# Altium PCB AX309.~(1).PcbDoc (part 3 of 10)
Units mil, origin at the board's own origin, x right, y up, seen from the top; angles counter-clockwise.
Board outline 5185 x 3614 mil, 4 copper layers (Top Layer, GND, Mid-Layer 1, Bottom Layer); 191 components, 352 nets, 1106 pads, 425 vias.
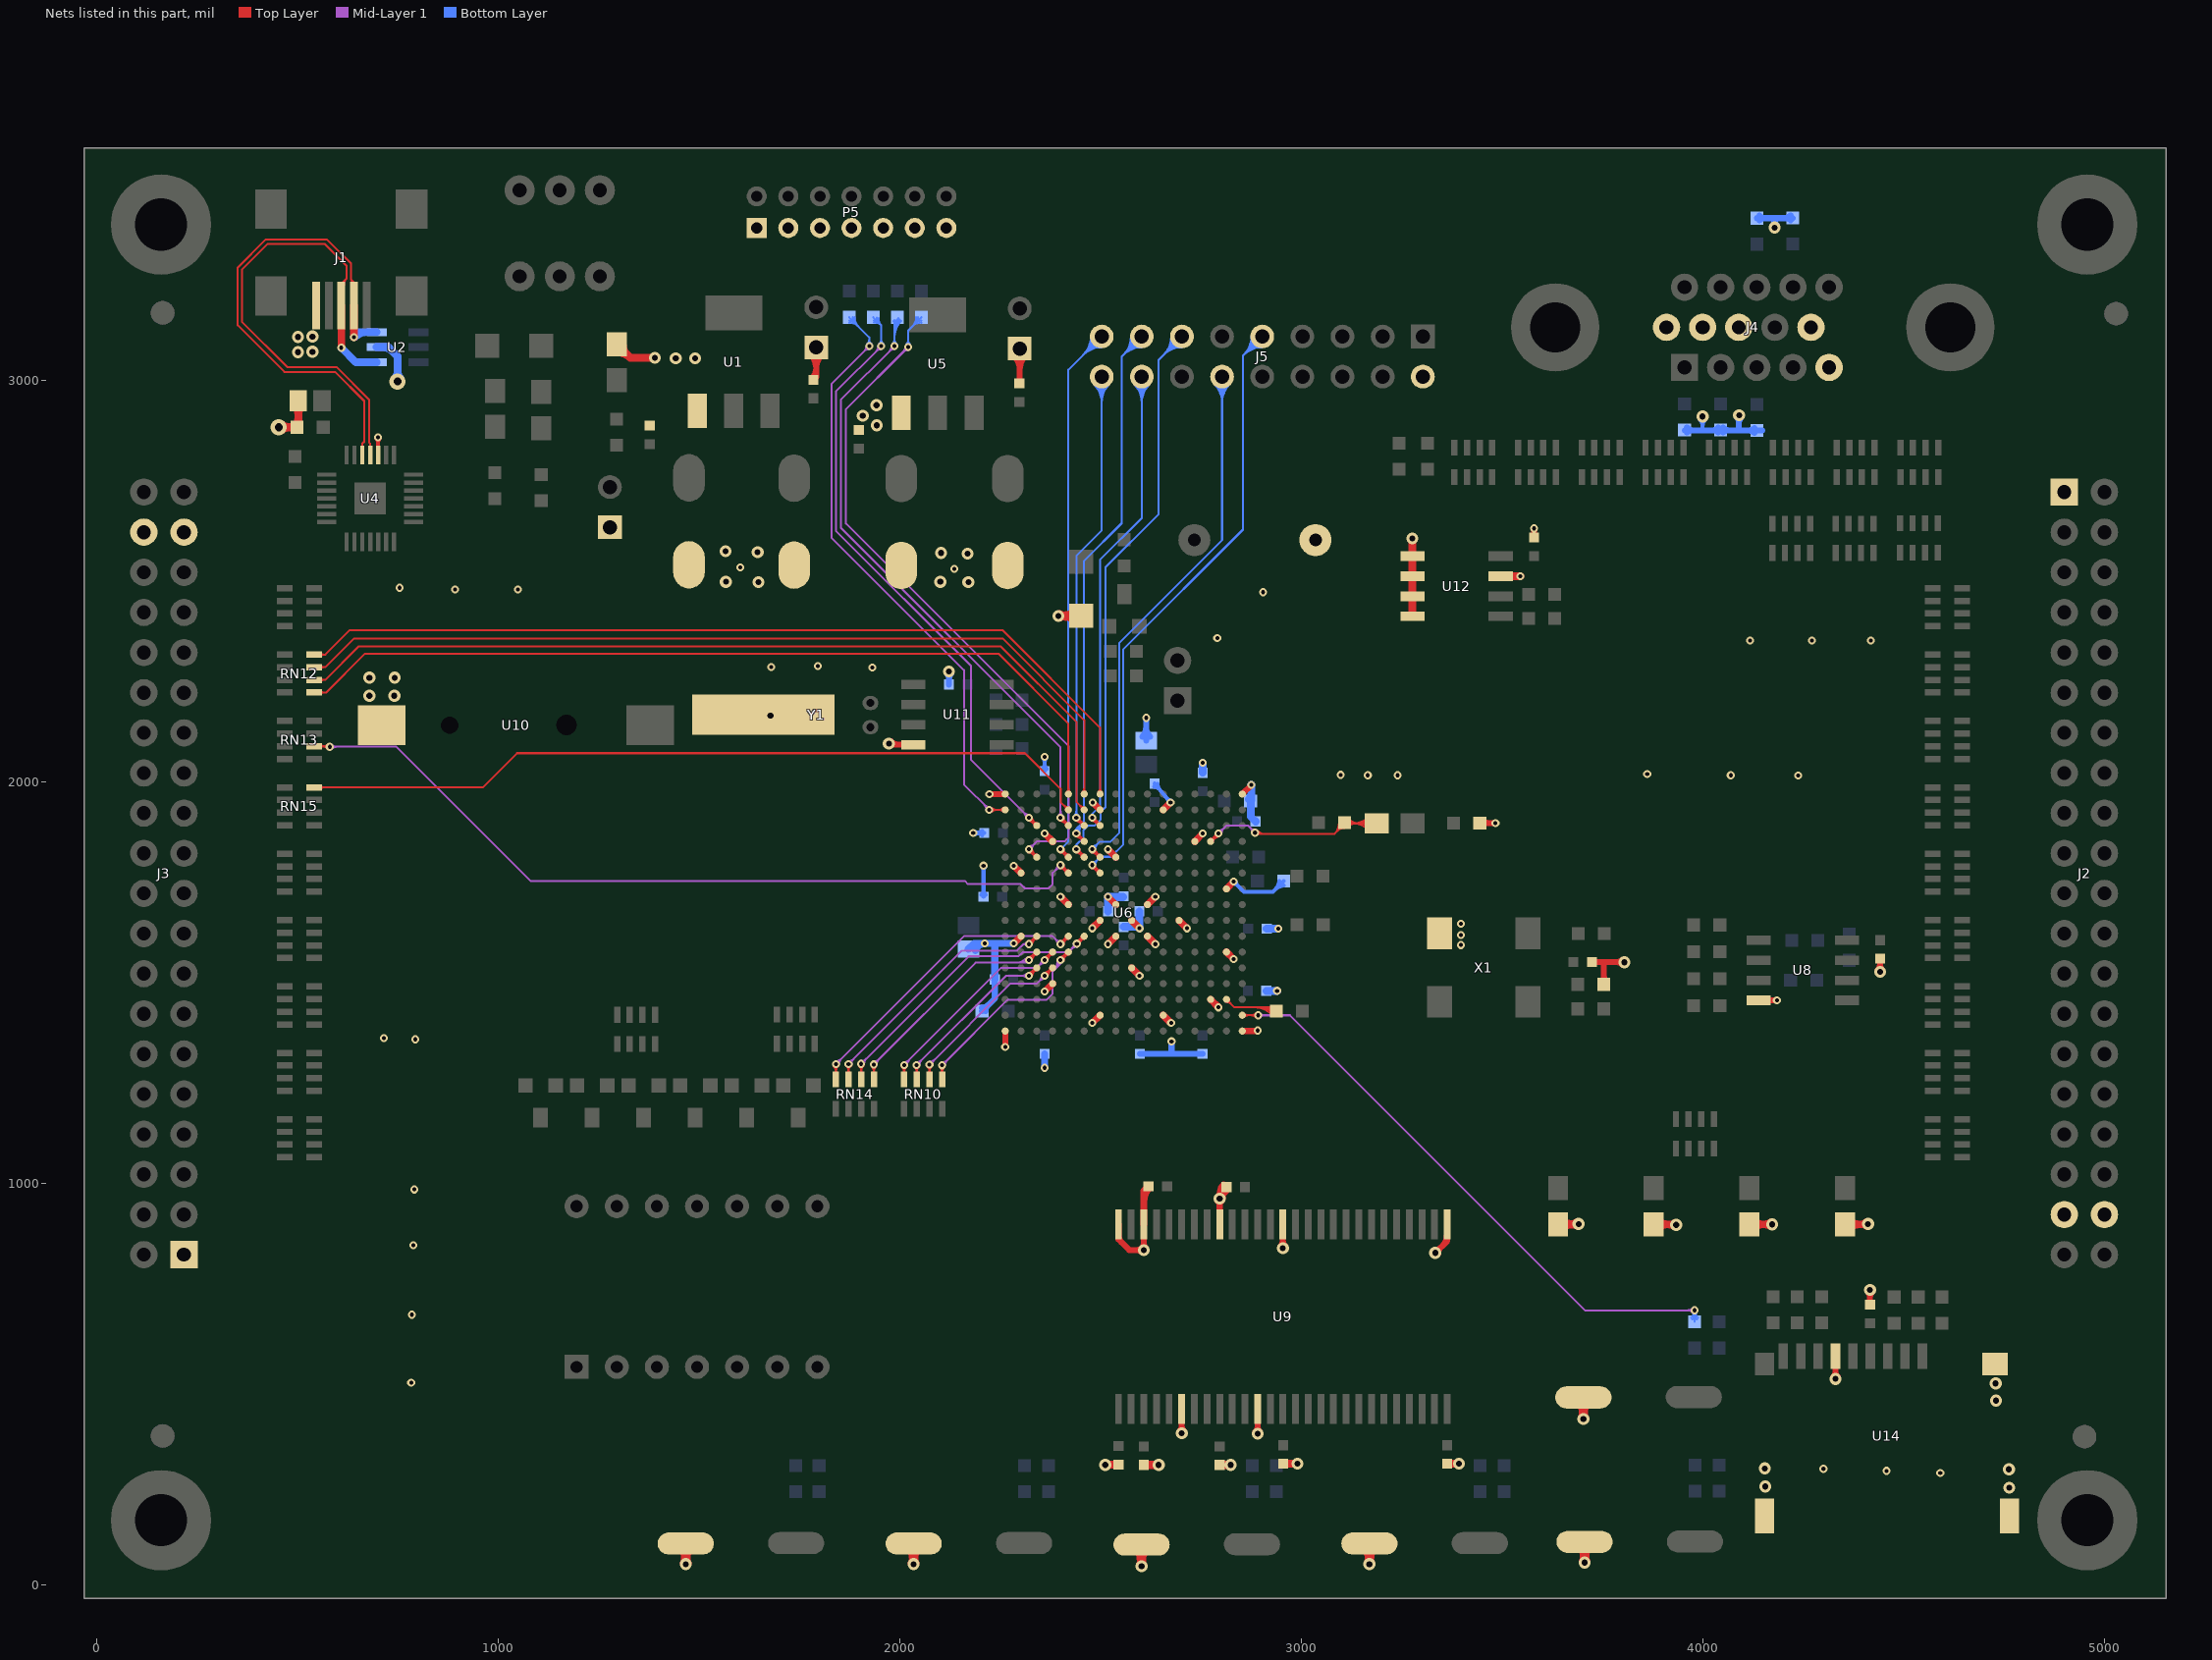
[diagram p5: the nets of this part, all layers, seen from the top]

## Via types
v1: diameter 20, hole 10, Top Layer to Bottom Layer, 328 vias
v2: diameter 30, hole 15, Top Layer to Bottom Layer, 95 vias
v3: diameter 40, hole 20, Top Layer to Bottom Layer, 2 vias

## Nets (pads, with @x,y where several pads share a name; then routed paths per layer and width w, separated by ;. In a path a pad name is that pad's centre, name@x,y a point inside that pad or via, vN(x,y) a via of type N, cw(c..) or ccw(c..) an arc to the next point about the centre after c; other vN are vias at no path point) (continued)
DIG0: RN14.7 U6.C7 | length 885.6
  Top Layer w5: v1@1867.19,1291.19 cw(c1854.39,1278.39) 1872.5,1278.39 cw(c1890.6,1278.39) v1@1877.8,1291.19 ; RN14.7@1868.7,1273.76 ccw(c1859.52,1282.93) 1872.5,1282.93 ccw(c1885.47,1282.93) RN14.7@1876.3,1273.76 ; RN14.7@1872.5,1258.15 v1(1872.5,1296.5) ; v1@2320.77,1602.69 ccw(c2318.06,1622.67) U6.C7@2335.52,1612.59 ; v1@2321.44,1597.74 ccw(c2319.79,1609.9) 2330.42,1603.76 ; v1(2321.78,1595.26) U6.C7@2341.46,1614.94 ; v1@2321.78,1602.76 ccw(c2321.78,1620.87) 2334.58,1608.06 ccw(c2347.39,1595.26) v1@2329.28,1595.26 ; v1@2323.75,1602.5 ccw(c2325.56,1609.16) 2331.54,1605.71 ; v1@2324.26,1594.92 cw(c2336.42,1593.27) 2330.28,1603.9 ; v1@2329.02,1597.23 cw(c2335.68,1599.04) 2332.23,1605.02 ; v1@2329.21,1594.25 cw(c2349.19,1591.54) U6.C7@2339.11,1609 ; U6.C7@2335.11,1614.94 cw(c2319.76,1614.94) 2330.61,1604.09 cw(c2341.46,1593.24) U6.C7@2341.46,1608.59 ; v1@2323.72,1602.5 ccw(c2325.55,1609.33) 2329.08,1603.21 cw(c2325.55,1609.33) v1@2323.72,1602.5 ; v1@2329.02,1597.2 cw(c2335.85,1599.03) 2329.73,1602.56 ccw(c2335.85,1599.03) v1@2329.02,1597.2
  Mid-Layer 1 w5: v1(1872.5,1296.5) 2155,1579 2292,1579 2308.26,1595.26 ; v1@1872.5,1304 ccw(c1872.5,1322.1) 1885.3,1309.3 ccw(c1898.1,1296.5) v1@1880,1296.5 ; v1@2315.42,1591.29 ccw(c2308.26,1586.82) 2308.26,1595.26 ; v1@2315.42,1599.23 cw(c2308.26,1603.69) 2308.26,1595.26 ; v1(2321.78,1595.26) 2308.26,1595.26
DIG1: RN10.5 U6.E6 | length 801.5
  Top Layer w5: v1@2100.18,1288.18 cw(c2087.38,1275.38) 2105.49,1275.38 cw(c2123.59,1275.38) v1@2110.79,1288.18 ; RN10.5@2101.69,1273.76 ccw(c2092.51,1282.93) 2105.49,1282.93 ccw(c2118.46,1282.93) RN10.5@2109.29,1273.76 ; RN10.5@2105.49,1258.15 v1(2105.49,1293.49) ; v1@2399.51,1563.32 ccw(c2396.8,1583.3) U6.E6@2414.26,1573.22 ; v1@2400.18,1558.37 ccw(c2398.53,1570.53) 2409.16,1564.39 ; v1(2400.52,1555.89) U6.E6@2420.2,1575.57 ; v1@2400.52,1563.39 ccw(c2400.52,1581.5) 2413.32,1568.69 ccw(c2426.13,1555.89) v1@2408.02,1555.89 ; v1@2402.49,1563.13 ccw(c2404.3,1569.79) 2410.28,1566.34 ; v1@2403,1555.55 cw(c2415.16,1553.9) 2409.02,1564.53 ; v1@2407.95,1554.88 cw(c2427.93,1552.17) U6.E6@2417.85,1569.63 ; 2410.97,1565.65 ccw(c2414.42,1559.67) v1@2407.76,1557.86 ; U6.E6@2413.85,1575.57 cw(c2398.5,1575.57) 2409.35,1564.72 cw(c2420.2,1553.87) U6.E6@2420.2,1569.22 ; v1@2407.76,1557.83 cw(c2414.59,1559.66) 2408.47,1563.19 ccw(c2414.59,1559.66) v1@2407.76,1557.83 ; v1@2402.46,1563.13 ccw(c2404.29,1569.96) 2407.82,1563.84 cw(c2404.29,1569.96) v1@2402.46,1563.13
  Mid-Layer 1 w5: v1(2105.49,1293.49) 2269,1457 2366,1457 2381,1472 2381,1527 2400.52,1546.52 v1(2400.52,1555.89) ; v1@2105.49,1300.99 ccw(c2105.49,1319.09) 2118.29,1306.29 ccw(c2131.09,1293.49) v1@2112.99,1293.49 ; 2381.09,1527.09 ccw(c2352.29,1555.89) v1@2393.02,1555.89 ; 2389.63,1535.63 ccw(c2369.36,1555.89) v1@2398.02,1555.89 ; 2398.16,1544.16 ccw(c2386.43,1555.89) v1@2403.02,1555.89
DIG2: RN10.7 U6.C5 | length 695.9
  Top Layer w5: v1@2036.7,1288.7 cw(c2022.7,1274.7) RN10.7@2042.5,1274.7 ; RN10.7@2038.7,1273.76 ccw(c2029.52,1282.93) 2042.5,1282.93 ccw(c2055.47,1282.93) RN10.7@2046.3,1273.76 ; RN10.7@2042.5,1258.15 v1@2042.5,1296.5 ; RN10.7@2042.5,1277.09 cw(c2058.91,1277.09) v1@2047.3,1288.7 ; v1@2320.77,1523.95 ccw(c2318.06,1543.93) U6.C5@2335.52,1533.85 ; v1@2321.44,1519 ccw(c2319.79,1531.16) 2330.42,1525.02 ; v1(2321.78,1516.52) U6.C5@2341.46,1536.2 ; v1@2321.78,1524.02 ccw(c2321.78,1542.13) 2334.58,1529.32 ccw(c2347.39,1516.52) v1@2329.28,1516.52 ; v1@2323.75,1523.76 ccw(c2325.56,1530.42) 2331.54,1526.97 ; v1@2324.26,1516.18 cw(c2336.42,1514.53) 2330.28,1525.16 ; v1@2329.02,1518.49 cw(c2335.68,1520.3) 2332.23,1526.28 ; v1@2329.21,1515.51 cw(c2349.19,1512.8) U6.C5@2339.11,1530.26 ; U6.C5@2335.11,1536.2 cw(c2319.76,1536.2) 2330.61,1525.35 cw(c2341.46,1514.5) U6.C5@2341.46,1529.85 ; v1@2323.72,1523.76 ccw(c2325.55,1530.59) 2329.08,1524.47 cw(c2325.55,1530.59) v1@2323.72,1523.76 ; v1@2329.02,1518.46 cw(c2335.85,1520.29) 2329.73,1523.82 ccw(c2335.85,1520.29) v1@2329.02,1518.46
  Mid-Layer 1 w5: v1(2042,1294) 2264.52,1516.52 v1(2321.78,1516.52) ; v1@2042,1301.5 ccw(c2042,1319.61) 2054.8,1306.8 ccw(c2067.61,1294) v1@2049.5,1294 ; v1@2316.48,1511.22 ccw(c2303.67,1498.41) 2303.67,1516.52 ccw(c2303.67,1534.63) v1@2316.48,1521.82
DIG3: RN14.6 U6.F7 | length 976.8
  Top Layer w5: v1@1898.69,1291.69 cw(c1885.89,1278.89) 1903.99,1278.89 cw(c1922.1,1278.89) v1@1909.3,1291.69 ; RN14.6@1900.19,1273.76 ccw(c1891.02,1282.93) 1903.99,1282.93 ccw(c1916.97,1282.93) RN14.6@1907.79,1273.76 ; RN14.6@1903.99,1258.15 v1(1903.99,1296.99) ; v1@2440.26,1603.83 ccw(c2438.55,1621.02) U6.F7@2453.51,1612.38 ; v1@2440.75,1598.86 ccw(c2439.74,1609.08) 2448.64,1603.95 ; v1(2441,1596.37) U6.F7@2459.57,1614.94 ; v1@2441,1603.87 ccw(c2441,1621.98) 2453.8,1609.17 ccw(c2466.61,1596.37) v1@2448.5,1596.37 ; v1@2443.49,1596.12 cw(c2453.71,1595.11) 2448.58,1604.01 ; v1@2443.64,1603.39 ccw(c2445.34,1607.93) 2449.54,1605.5 ; v1@2448.02,1599.01 cw(c2452.56,1600.71) 2450.13,1604.91 ; v1@2448.46,1595.63 cw(c2465.65,1593.92) U6.F7@2457.01,1608.88 ; U6.F7@2453.22,1614.94 cw(c2437.87,1614.94) 2448.72,1604.09 cw(c2459.57,1593.24) U6.F7@2459.57,1608.59 ; v1@2442.94,1603.61 ccw(c2445.13,1611.78) 2449.36,1604.46 cw(c2445.13,1611.78) v1@2442.94,1603.61 ; v1@2448.24,1598.31 cw(c2456.41,1600.5) 2449.09,1604.73 ccw(c2456.41,1600.5) v1@2448.24,1598.31
  Mid-Layer 1 w5: v1(1903.99,1296.99) 2172,1565 2296,1565 2306,1575 2419.63,1575 v1(2441,1596.37) ; v1@1903.99,1304.49 ccw(c1903.99,1322.6) 1916.8,1309.8 ccw(c1929.6,1296.99) v1@1911.49,1296.99 ; v1@2433.5,1596.37 cw(c2415.39,1596.37) 2428.2,1583.57 cw(c2441,1570.76) v1@2441,1588.87
DIG4: RN10.8 U6.D6 | length 780.1
  Top Layer w5: v1@2005.7,1288.7 cw(c1992.89,1275.89) 2011,1275.89 cw(c2029.11,1275.89) v1@2016.3,1288.7 ; RN10.8@2007.2,1273.76 ccw(c1998.03,1282.93) 2011,1282.93 ccw(c2023.97,1282.93) RN10.8@2014.8,1273.76 ; RN10.8@2011,1258.15 v1(2011,1294) ; v1@2360.14,1563.32 ccw(c2357.43,1583.3) U6.D6@2374.89,1573.22 ; v1@2360.81,1558.37 ccw(c2359.16,1570.53) 2369.79,1564.39 ; v1(2361.15,1555.89) U6.D6@2380.83,1575.57 ; v1@2361.15,1563.39 ccw(c2361.15,1581.5) 2373.95,1568.69 ccw(c2386.76,1555.89) v1@2368.65,1555.89 ; v1@2363.63,1555.55 cw(c2375.79,1553.9) 2369.65,1564.53 ; v1@2368.58,1554.88 cw(c2388.56,1552.17) U6.D6@2378.48,1569.63 ; 2370.91,1566.34 cw(c2364.93,1569.79) v1@2363.12,1563.13 ; 2371.6,1565.65 ccw(c2375.05,1559.67) v1@2368.39,1557.86 ; U6.D6@2374.48,1575.57 cw(c2359.13,1575.57) 2369.98,1564.72 cw(c2380.83,1553.87) U6.D6@2380.83,1569.22 ; v1@2363.09,1563.13 ccw(c2364.92,1569.96) 2368.45,1563.84 cw(c2364.92,1569.96) v1@2363.09,1563.13 ; v1@2368.39,1557.83 cw(c2375.22,1559.66) 2369.1,1563.19 ccw(c2375.22,1559.66) v1@2368.39,1557.83
  Mid-Layer 1 w5: v1(2011,1294) 2253.2,1536.2 2341.46,1536.2 v1(2361.15,1555.89) ; v1@2011,1301.5 ccw(c2011,1319.61) 2023.8,1306.8 ccw(c2036.61,1294) v1@2018.5,1294 ; v1@2353.65,1555.89 cw(c2335.54,1555.89) 2348.35,1543.09 cw(c2361.15,1530.28) v1@2361.15,1548.39
DIG5: RN14.8 U6.E7 | length 1023.3
  Top Layer w5: v1@1835.7,1290.7 cw(c1822.89,1277.89) 1841,1277.89 cw(c1859.11,1277.89) v1@1846.3,1290.7 ; RN14.8@1837.2,1273.76 ccw(c1828.03,1282.93) 1841,1282.93 ccw(c1853.97,1282.93) RN14.8@1844.8,1273.76 ; RN14.8@1841,1258.15 v1(1841,1296) ; v1@2399.51,1602.69 ccw(c2396.8,1622.67) U6.E7@2414.26,1612.59 ; v1@2400.18,1597.74 ccw(c2398.53,1609.9) 2409.16,1603.76 ; v1(2400.52,1595.26) U6.E7@2420.2,1614.94 ; v1@2400.52,1602.76 ccw(c2400.52,1620.87) 2413.32,1608.06 ccw(c2426.13,1595.26) v1@2408.02,1595.26 ; v1@2402.49,1602.5 ccw(c2404.3,1609.16) 2410.28,1605.71 ; v1@2403,1594.92 cw(c2415.16,1593.27) 2409.02,1603.9 ; v1@2407.76,1597.23 cw(c2414.42,1599.04) 2410.97,1605.02 ; v1@2407.95,1594.25 cw(c2427.93,1591.54) U6.E7@2417.85,1609 ; U6.E7@2413.85,1614.94 cw(c2398.5,1614.94) 2409.35,1604.09 cw(c2420.2,1593.24) U6.E7@2420.2,1608.59 ; v1@2402.46,1602.5 ccw(c2404.29,1609.33) 2407.82,1603.21 cw(c2404.29,1609.33) v1@2402.46,1602.5 ; v1@2407.76,1597.2 cw(c2414.59,1599.03) 2408.47,1602.56 ccw(c2414.59,1599.03) v1@2407.76,1597.2
  Mid-Layer 1 w5: v1(1841,1296) 2160,1615 2380.78,1615 v1(2400.52,1595.26) ; v1@1841,1303.5 ccw(c1841,1321.61) 1853.8,1308.8 ccw(c1866.61,1296) v1@1848.5,1296 ; v1@2393.02,1595.26 ccw(c2374.91,1595.26) 2387.72,1608.06 ccw(c2400.52,1620.87) v1@2400.52,1602.76
DIG6: RN10.6 U6.D5 | length 701.4
  Top Layer w5: v1@2068.69,1289.69 cw(c2055.89,1276.89) 2073.99,1276.89 cw(c2092.1,1276.89) v1@2079.3,1289.69 ; RN10.6@2070.19,1273.76 ccw(c2061.02,1282.93) 2073.99,1282.93 ccw(c2086.97,1282.93) RN10.6@2077.79,1273.76 ; RN10.6@2073.99,1258.15 v1(2073.99,1294.99) ; v1@2360.14,1523.95 ccw(c2357.43,1543.93) U6.D5@2374.89,1533.85 ; v1@2360.81,1519 ccw(c2359.16,1531.16) 2369.79,1525.02 ; v1(2361.15,1516.52) U6.D5@2380.83,1536.2 ; v1@2361.15,1524.02 ccw(c2361.15,1542.13) 2373.95,1529.32 ccw(c2386.76,1516.52) v1@2368.65,1516.52 ; v1@2363.63,1516.18 cw(c2375.79,1514.53) 2369.65,1525.16 ; v1@2368.39,1518.49 cw(c2375.05,1520.3) 2371.6,1526.28 ; v1@2368.58,1515.51 cw(c2388.56,1512.8) U6.D5@2378.48,1530.26 ; 2370.91,1526.97 cw(c2364.93,1530.42) v1@2363.12,1523.76 ; U6.D5@2374.48,1536.2 cw(c2359.13,1536.2) 2369.98,1525.35 cw(c2380.83,1514.5) U6.D5@2380.83,1529.85 ; v1@2363.09,1523.76 ccw(c2364.92,1530.59) 2368.45,1524.47 cw(c2364.92,1530.59) v1@2363.09,1523.76 ; v1@2368.39,1518.46 cw(c2375.22,1520.29) 2369.1,1523.82 ccw(c2375.22,1520.29) v1@2368.39,1518.46
  Mid-Layer 1 w5: v1(2073.99,1294.99) 2276,1497 2341.63,1497 v1(2361.15,1516.52) ; v1@2073.99,1302.49 ccw(c2073.99,1320.6) 2086.8,1307.8 ccw(c2099.6,1294.99) v1@2081.49,1294.99 ; v1@2353.65,1516.52 cw(c2335.54,1516.52) 2348.35,1503.72 cw(c2361.15,1490.91) v1@2361.15,1509.02
DIG7: RN14.5 U6.C6 | length 858.3
  Top Layer w5: v1@1930.18,1290.21 cw(c1917.38,1277.41) 1935.49,1277.41 cw(c1953.59,1277.41) v1@1940.79,1290.21 ; RN14.5@1931.69,1273.76 ccw(c1922.51,1282.93) 1935.49,1282.93 ccw(c1948.46,1282.93) RN14.5@1939.29,1273.76 ; RN14.5@1935.49,1258.15 v1(1935.49,1295.51) ; v1@2320.77,1563.32 ccw(c2318.06,1583.3) U6.C6@2335.52,1573.22 ; v1@2321.44,1558.37 ccw(c2319.79,1570.53) 2330.42,1564.39 ; v1(2321.78,1555.89) U6.C6@2341.46,1575.57 ; v1@2321.78,1563.39 ccw(c2321.78,1581.5) 2334.58,1568.69 ccw(c2347.39,1555.89) v1@2329.28,1555.89 ; v1@2323.75,1563.13 ccw(c2325.56,1569.79) 2331.54,1566.34 ; v1@2324.26,1555.55 cw(c2336.42,1553.9) 2330.28,1564.53 ; v1@2329.21,1554.88 cw(c2349.19,1552.17) U6.C6@2339.11,1569.63 ; 2332.23,1565.65 ccw(c2335.68,1559.67) v1@2329.02,1557.86 ; U6.C6@2335.11,1575.57 cw(c2319.76,1575.57) 2330.61,1564.72 cw(c2341.46,1553.87) U6.C6@2341.46,1569.22 ; v1@2329.02,1557.83 cw(c2335.85,1559.66) 2329.73,1563.19 ccw(c2335.85,1559.66) v1@2329.02,1557.83 ; v1@2323.72,1563.13 ccw(c2325.55,1569.96) 2329.08,1563.84 cw(c2325.55,1569.96) v1@2323.72,1563.13
  Mid-Layer 1 w5: v1(1935.49,1295.51) 2188.98,1549 2314.89,1549 v1(2321.78,1555.89) ; v1@1935.49,1303.01 ccw(c1935.49,1321.12) 1948.29,1308.32 ccw(c1961.09,1295.51) v1@1942.99,1295.51 ; 2287.04,1549 ccw(c2287.04,1590.63) v1@2316.48,1561.19 ; 2299.11,1549 ccw(c2299.11,1578.56) v1@2320.01,1557.66 ; 2311.18,1549 ccw(c2311.18,1566.48) v1@2323.55,1554.12
DM: J1.2 U2.3 U4.5 | length 1328.1
  Top Layer w5: J1.2@634.29,3239.43 ccw(c626.41,3244.41) 633,3251 ; 637.42,3246.58 cw(c631.83,3240.99) J1.2@638.52,3236.76 ; J1.2@640.5,3186.3 640.5,3243.5 633,3251 ; U4.5@659.27,2834.3 ccw(c654.46,2839.1) 661.26,2839.1 ccw(c668.06,2839.1) U4.5@663.25,2834.3 ; U4.5@661.26,2814 661.26,2842.26 666,2847 666,2948.44 593.44,3021 467,3021 351,3137 351,3281 421,3351 573,3351 633,3291 633,3251
  Top Layer w19: v1(640.5,3107) J1.2@640.5,3186.3
  Bottom Layer w19: v1(640.5,3107) 653.5,3120 U2.3@697,3120 ; v1@640.85,3106.65 cw(c673.09,3074.41) U2.3@673.09,3120
DP: J1.3 U2.1 U4.4 | length 1329.8
  Top Layer w5: J1.3@609,3186.3 609,3241 622,3254 ; J1.3@611.32,3235.86 cw(c624.19,3237.78) 614.99,3246.99 ; J1.3@616.26,3236.6 cw(c636.39,3239.61) 622,3254 ; U4.4@678.95,2834.3 ccw(c674.15,2839.1) 680.94,2839.1 ccw(c687.74,2839.1) U4.4@682.94,2834.3 ; U4.4@680.94,2814 680.94,2842.06 677.97,2845.03 677.97,2952.03 597,3033 474,3033 362,3145 362,3276.44 425.56,3340 567,3340 622,3285 622,3254
  Top Layer w19: v1(609,3081) J1.3@609,3186.3
  Bottom Layer w19: v1(609,3081) 645,3045 U2.1@697,3045
E11: RN13.6 U6.E11 | length 2330.2
  Top Layer w5: RN13.6@541.15,2088.26 v1@578.74,2088.26 ; RN13.6@556.76,2084.46 cw(c565.93,2075.28) 565.93,2088.26 cw(c565.93,2101.23) RN13.6@556.76,2092.06 ; RN13.6@558.86,2088.26 cw(c558.86,2065.86) v1@574.7,2081.7 ; 564.93,2088.26 ccw(c564.93,2102.07) v1@574.7,2092.3 ; v1@2399.51,1784.68 cw(c2396.8,1764.7) U6.E11@2414.26,1774.78 ; v1@2400.18,1789.63 cw(c2398.53,1777.47) 2409.16,1783.61 ; v1@2400.52,1784.61 cw(c2400.52,1766.5) 2413.32,1779.31 cw(c2426.13,1792.11) v1@2408.02,1792.11 ; v1(2400.52,1792.11) U6.E11@2420.2,1772.43 ; v1@2402.49,1784.87 cw(c2404.3,1778.21) 2410.28,1781.66 ; v1@2403,1792.45 ccw(c2415.16,1794.1) 2409.02,1783.47 ; v1@2407.95,1793.12 ccw(c2427.93,1795.83) U6.E11@2417.85,1778.37 ; 2410.97,1782.35 cw(c2414.42,1788.33) v1@2407.76,1790.14 ; U6.E11@2413.85,1772.43 ccw(c2398.5,1772.43) 2409.35,1783.28 ccw(c2420.2,1794.13) U6.E11@2420.2,1778.78 ; v1@2407.76,1790.17 ccw(c2414.59,1788.34) 2408.47,1784.81 cw(c2414.59,1788.34) v1@2407.76,1790.17 ; v1@2402.46,1784.87 cw(c2404.29,1778.04) 2407.82,1784.16 ccw(c2404.29,1778.04) v1@2402.46,1784.87
  Mid-Layer 1 w5: v1(580,2087) 746,2087 1081,1752 2163,1752 2170,1745 2301,1745 2312,1734 2370,1734 2381,1745 2381,1772.59 v1(2400.52,1792.11) ; v1@585.3,2081.7 cw(c598.11,2068.89) 598.11,2087 cw(c598.11,2105.11) v1@585.3,2092.3 ; v1@2393.02,1792.11 cw(c2374.91,1792.11) 2387.72,1779.31 cw(c2400.52,1766.5) v1@2400.52,1784.61
E12: J5.17 U6.E12 | length 1750.7
  Top Layer w5: v1@2399.51,1824.05 cw(c2396.8,1804.07) U6.E12@2414.26,1814.15 ; v1@2400.18,1829 cw(c2398.53,1816.84) 2409.16,1822.98 ; v1@2400.52,1823.98 cw(c2400.52,1805.87) 2413.32,1818.68 cw(c2426.13,1831.48) v1@2408.02,1831.48 ; v1(2400.52,1831.48) U6.E12@2420.2,1811.8 ; v1@2402.49,1824.24 cw(c2404.3,1817.58) 2410.28,1821.03 ; v1@2403,1831.82 ccw(c2415.16,1833.47) 2409.02,1822.84 ; v1@2407.76,1829.51 ccw(c2414.42,1827.7) 2410.97,1821.72 ; v1@2407.95,1832.49 ccw(c2427.93,1835.2) U6.E12@2417.85,1817.74 ; U6.E12@2413.85,1811.8 ccw(c2398.5,1811.8) 2409.35,1822.65 ccw(c2420.2,1833.5) U6.E12@2420.2,1818.15 ; v1@2402.46,1824.24 cw(c2404.29,1817.41) 2407.82,1823.53 ccw(c2404.29,1817.41) v1@2402.46,1824.24 ; v1@2407.76,1829.54 ccw(c2414.59,1827.71) 2408.47,1824.18 cw(c2414.59,1827.71) v1@2407.76,1829.54
  Bottom Layer w5: v1(2400.52,1831.48) 2420,1850.96 2420,3026.17 J5.17@2503,3109.17 ; J5.17@2475.97,3109.17 cw(c2410.72,3109.17) 2456.86,3063.03 cw(c2503,3016.9) J5.17@2503,3082.15 ; J5.17@2480.97,3109.17 cw(c2427.79,3109.17) 2465.4,3071.57 cw(c2503,3033.97) J5.17@2503,3087.15 ; J5.17@2485.97,3109.17 cw(c2444.86,3109.17) 2473.93,3080.11 cw(c2503,3051.04) J5.17@2503,3092.15
E15: RN15.8 U6.E15 | length 2036.5
  Top Layer w5: RN15.8@541.15,1985.88 961.88,1985.88 1047,2071 2312,2071 2401,1982 2401,1949.11 U6.E15@2420.2,1929.91 ; RN15.8@556.76,1982.08 cw(c565.93,1972.9) 565.93,1985.88 cw(c565.93,1998.85) RN15.8@556.76,1989.67 ; U6.E15@2413.85,1929.91 ccw(c2398.5,1929.91) 2409.35,1940.76 ccw(c2420.2,1951.61) U6.E15@2420.2,1936.26
E16: RN12.5 U6.E16 | length 2211.3
  Top Layer w5: RN12.5@541.15,2222.14 571.14,2222.14 668,2319 2246,2319 2420.2,2144.8 U6.E16@2420.2,1969.28 ; RN12.5@556.76,2218.34 cw(c565.93,2209.16) 565.93,2222.14 cw(c565.93,2235.11) RN12.5@556.76,2225.94 ; U6.E16@2415.71,1973.77 ccw(c2404.85,1984.63) 2420.2,1984.63 ccw(c2435.55,1984.63) U6.E16@2424.7,1973.77
F12: J5.13 U6.F12 | length 1838
  Top Layer w5: v1@2438.88,1824.05 cw(c2436.17,1804.07) U6.F12@2453.63,1814.15 ; v1@2439.55,1829 cw(c2437.9,1816.84) 2448.53,1822.98 ; v1@2439.89,1823.98 cw(c2439.89,1805.87) 2452.69,1818.68 cw(c2465.5,1831.48) v1@2447.39,1831.48 ; v1(2439.89,1831.48) U6.F12@2459.57,1811.8 ; v1@2442.37,1831.82 ccw(c2454.53,1833.47) 2448.39,1822.84 ; v1@2447.13,1829.51 ccw(c2453.79,1827.7) 2450.34,1821.72 ; v1@2447.32,1832.49 ccw(c2467.3,1835.2) U6.F12@2457.22,1817.74 ; 2449.65,1821.03 ccw(c2443.67,1817.58) v1@2441.86,1824.24 ; U6.F12@2453.22,1811.8 ccw(c2437.87,1811.8) 2448.72,1822.65 ccw(c2459.57,1833.5) U6.F12@2459.57,1818.15 ; v1@2441.83,1824.24 cw(c2443.66,1817.41) 2447.19,1823.53 ccw(c2443.66,1817.41) v1@2441.83,1824.24 ; v1@2447.13,1829.54 ccw(c2453.96,1827.71) 2447.84,1824.18 cw(c2453.96,1827.71) v1@2447.13,1829.54
  Bottom Layer w5: v1@2436.92,1838.37 ccw(c2434.96,1842.89) 2439.89,1842.89 ; v1(2439.89,1831.48) 2439.89,1842.89 ; v1@2442.86,1838.37 cw(c2444.81,1842.89) 2439.89,1842.89 ; J5.13@2675.97,3109.17 cw(c2610.72,3109.17) 2656.86,3063.03 cw(c2703,3016.9) J5.13@2703,3082.15 ; J5.13@2680.97,3109.17 cw(c2627.79,3109.17) 2665.4,3071.57 cw(c2703,3033.97) J5.13@2703,3087.15 ; J5.13@2685.97,3109.17 cw(c2644.86,3109.17) 2673.93,3080.11 cw(c2703,3051.04) J5.13@2703,3092.15 ; J5.13@2703,3109.17 2645,3051.17 2645,2667 2513,2535 2513,1937 2500,1924 2500,1905 2486,1891 2470,1891 2458,1879 2458,1861 2439.89,1842.89
F13: J5.15 U6.F13 | length 1826.1
  Top Layer w5: v1@2438.88,1863.42 cw(c2436.17,1843.44) U6.F13@2453.63,1853.52 ; v1@2439.55,1868.37 cw(c2437.9,1856.21) 2448.53,1862.35 ; v1@2439.89,1863.35 cw(c2439.89,1845.24) 2452.69,1858.05 cw(c2465.5,1870.85) v1@2447.39,1870.85 ; v1(2439.89,1870.85) U6.F13@2459.57,1851.17 ; v1@2442.37,1871.19 ccw(c2454.53,1872.84) 2448.39,1862.21 ; v1@2447.32,1871.86 ccw(c2467.3,1874.57) U6.F13@2457.22,1857.11 ; 2449.65,1860.4 ccw(c2443.67,1856.95) v1@2441.86,1863.61 ; 2450.34,1861.09 cw(c2453.79,1867.07) v1@2447.13,1868.88 ; U6.F13@2453.22,1851.17 ccw(c2437.87,1851.17) 2448.72,1862.02 ccw(c2459.57,1872.87) U6.F13@2459.57,1857.52 ; v1@2441.83,1863.61 cw(c2443.66,1856.78) 2447.19,1862.9 ccw(c2443.66,1856.78) v1@2441.83,1863.61 ; v1@2447.13,1868.91 ccw(c2453.96,1867.08) 2447.84,1863.55 cw(c2453.96,1867.08) v1@2447.13,1868.91
  Bottom Layer w5: v1@2436.58,1877.58 ccw(c2433.98,1882.89) 2439.89,1882.89 ; v1@2437.39,1870.7 cw(c2457.67,1871.94) 2443.3,1886.3 ; v1(2439.89,1870.85) 2439.89,1882.89 ; v1@2442.38,1871 cw(c2472.46,1872.85) 2451.15,1894.15 ; v1@2443.19,1877.58 cw(c2445.8,1882.89) 2439.89,1882.89 ; v1@2447.37,1871.31 cw(c2487.24,1873.76) 2459,1902 ; J5.15@2575.97,3109.17 cw(c2510.72,3109.17) 2556.86,3063.03 cw(c2603,3016.9) J5.15@2603,3082.15 ; J5.15@2580.97,3109.17 cw(c2527.79,3109.17) 2565.4,3071.57 cw(c2603,3033.97) J5.15@2603,3087.15 ; J5.15@2585.97,3109.17 cw(c2544.86,3109.17) 2573.93,3080.11 cw(c2603,3051.04) J5.15@2603,3092.15 ; J5.15@2603,3109.17 2553,3059.17 2553,2644 2459,2550 2459,1902 ; 2439.89,1882.89 2459,1902
F14: J5.18 U6.F14 | length 1584.1
  Top Layer w5: v1@2438.88,1902.79 cw(c2436.17,1882.81) U6.F14@2453.63,1892.89 ; v1@2439.55,1907.74 cw(c2437.9,1895.58) 2448.53,1901.72 ; v1@2439.89,1902.72 cw(c2439.89,1884.61) 2452.69,1897.42 cw(c2465.5,1910.22) v1@2447.39,1910.22 ; v1(2439.89,1910.22) U6.F14@2459.57,1890.54 ; v1@2442.37,1910.56 ccw(c2454.53,1912.21) 2448.39,1901.58 ; v1@2447.13,1908.25 ccw(c2453.79,1906.44) 2450.34,1900.46 ; v1@2447.32,1911.23 ccw(c2467.3,1913.94) U6.F14@2457.22,1896.48 ; 2449.65,1899.77 ccw(c2443.67,1896.32) v1@2441.86,1902.98 ; U6.F14@2453.22,1890.54 ccw(c2437.87,1890.54) 2448.72,1901.39 ccw(c2459.57,1912.24) U6.F14@2459.57,1896.89 ; v1@2441.83,1902.98 cw(c2443.66,1896.15) 2447.19,1902.27 ccw(c2443.66,1896.15) v1@2441.83,1902.98 ; v1@2447.13,1908.28 ccw(c2453.96,1906.45) 2447.84,1902.92 cw(c2453.96,1906.45) v1@2447.13,1908.28
  Bottom Layer w5: v1@2434.59,1915.52 ccw(c2421.78,1928.33) 2439.89,1928.33 ccw(c2458,1928.33) v1@2445.19,1915.52 ; v1(2439.89,1910.22) 2439.89,2562.89 2503,2626 J5.18@2503,3009.17 ; J5.18@2483.89,2990.06 cw(c2437.75,2943.92) 2503,2943.92 cw(c2568.25,2943.92) J5.18@2522.11,2990.06 ; J5.18@2487.42,2993.6 cw(c2449.82,2955.99) 2503,2955.99 cw(c2556.18,2955.99) J5.18@2518.58,2993.6 ; J5.18@2490.96,2997.13 cw(c2461.89,2968.07) 2503,2968.07 cw(c2544.11,2968.07) J5.18@2515.04,2997.13
F15: RN12.6 U6.F15 | length 2282.9
  Top Layer w5: RN12.6@541.15,2253.63 568.63,2253.63 652,2337 2252,2337 2440,2149 2440,1949.48 U6.F15@2459.57,1929.91 ; RN12.6@556.76,2249.83 cw(c565.93,2240.66) 565.93,2253.63 cw(c565.93,2266.61) RN12.6@556.76,2257.43 ; U6.F15@2453.22,1929.91 ccw(c2437.87,1929.91) 2448.72,1940.76 ccw(c2459.57,1951.61) U6.F15@2459.57,1936.26
F16: RN12.7 U6.F16 | length 2261.2
  Top Layer w5: RN12.7@541.15,2285.13 568.84,2285.13 640.71,2357 2256,2357 2459.57,2153.43 U6.F16@2459.57,1969.28 ; RN12.7@556.76,2281.33 cw(c565.93,2272.15) 565.93,2285.13 cw(c565.93,2298.1) RN12.7@556.76,2288.93 ; U6.F16@2455.08,1973.77 ccw(c2444.22,1984.63) 2459.57,1984.63 ccw(c2474.92,1984.63) U6.F16@2464.07,1973.77
FPGA_DONE: LED5.1 R17.1 U6.P13 | length 1043.5
  Top Layer w5: U6.P13@2774.54,1851.17 v1(2794.22,1870.85) ; U6.P13@2774.54,1857.52 ccw(c2774.54,1872.87) 2785.39,1862.02 ccw(c2796.24,1851.17) U6.P13@2780.89,1851.17 ; U6.P13@2776.89,1857.11 ccw(c2766.81,1874.57) v1@2786.79,1871.86 ; U6.P13@2780.48,1853.52 cw(c2797.94,1843.44) v1@2795.23,1863.42 ; 2783.77,1861.09 ccw(c2780.32,1867.07) v1@2786.98,1868.88 ; 2784.46,1860.4 cw(c2790.44,1856.95) v1@2792.25,1863.61 ; 2785.58,1862.35 cw(c2796.21,1856.21) v1@2794.56,1868.37 ; 2785.72,1862.21 ccw(c2779.58,1872.84) v1@2791.74,1871.19 ; v1@2786.72,1870.85 cw(c2768.61,1870.85) 2781.42,1858.05 cw(c2794.22,1845.24) v1@2794.22,1863.35 ; v1(2885,1873) 2888,1870 3083,1870 ; v1@2886.77,1874.77 ccw(c2898.28,1886.28) 2898.28,1870 ; v1@2890.3,1867.7 cw(c2895.86,1862.14) 2895.86,1870 ; v1@2890.3,1878.3 ccw(c2910.35,1898.35) 2910.35,1870 ; 3090.08,1877.08 cw(c3108,1859.15) R17.1@3108,1884.5 ; 3091.48,1878.48 ccw(c3072.13,1897.84) R17.1@3099.5,1897.96 ; R17.1@3094.5,1897.94 cw(c3055.24,1897.76) 3083,1870 ; R17.1@3114.01,1904.01 ccw(c3133.35,1923.35) 3133.35,1896 ; R17.1@3117.55,1888.45 cw(c3135.76,1870.24) 3135.76,1896 ; R17.1@3117.55,1907.55 ccw(c3145.42,1935.42) 3145.42,1896 ; LED5.1@3167.09,1880.09 ccw(c3128.68,1841.68) 3128.68,1896 ccw(c3128.68,1950.32) LED5.1@3167.09,1911.91 ; LED5.1@3170.63,1883.63 ccw(c3140.75,1853.75) 3140.75,1896 ccw(c3140.75,1938.25) LED5.1@3170.63,1908.37 ; LED5.1@3174.16,1887.16 ccw(c3152.82,1865.82) 3152.82,1896 ccw(c3152.82,1926.18) LED5.1@3174.16,1904.84 ; LED5.1@3188,1896 3109,1896 3083,1870 ; v1@2786.98,1868.91 cw(c2780.15,1867.08) 2786.27,1863.55 ccw(c2780.15,1867.08) v1@2786.98,1868.91 ; 2786.92,1862.9 cw(c2790.45,1856.78) 2792.28,1863.61 ccw(c2790.45,1856.78) 2786.92,1862.9
  Mid-Layer 1 w5: v1(2794.22,1870.85) 2813.91,1890.54 2867.46,1890.54 v1(2885,1873) ; v1@2794.22,1878.35 ccw(c2794.22,1896.46) 2807.02,1883.65 ccw(c2819.83,1870.85) v1@2801.72,1870.85 ; v1@2877.5,1873 ccw(c2859.39,1873) 2872.2,1885.8 ccw(c2885,1898.61) v1@2885,1880.5
FPGA_INIT_B: R9.1 U6.R3 | length 309
  Top Layer w5: U6.R3@2813.91,1451.11 cw(c2813.91,1435.76) 2824.76,1446.61 cw(c2835.61,1457.46) U6.R3@2820.26,1457.46 ; U6.R3@2813.91,1457.46 2833.37,1438 R9.1@2938,1438 ; 2881.27,1438 cw(c2881.27,1371.27) R9.1@2928.45,1418.45 ; 2893.34,1438 cw(c2893.34,1383.34) R9.1@2931.99,1421.99 ; 2905.41,1438 cw(c2905.41,1395.41) R9.1@2935.53,1425.53 ; 2917.48,1438 cw(c2917.48,1407.48) R9.1@2939.06,1429.06
FPGA_PROG_B: R22.1 U6.T2 | length 1696.7
  Top Layer w5: U6.T2@2853.28,1418.09 v1@2892.55,1418.09 ; U6.T2@2857.77,1413.6 cw(c2868.63,1402.74) 2868.63,1418.09 cw(c2868.63,1433.44) U6.T2@2857.77,1422.59 ; 2874.31,1418.09 cw(c2874.31,1399.67) v1@2887.34,1412.7 ; 2874.77,1418.09 ccw(c2874.77,1435.88) v1@2887.34,1423.3
  Mid-Layer 1 w5: v1(2892.65,1418) 2972,1418 3707,683 v1(3980,683) ; v1@2897.95,1412.7 cw(c2910.75,1399.89) 2910.75,1418 cw(c2910.75,1436.11) v1@2897.95,1423.3 ; v1@3974.7,677.7 ccw(c3961.89,664.89) 3961.89,683 ccw(c3961.89,701.11) v1@3974.7,688.3
  Bottom Layer w5: R22.1@3971.31,664.33 ccw(c3955.61,683) v1(3980,683) ; R22.1@3974.53,660.5 ccw(c3964.64,672.26) 3980,672.26 ccw(c3995.36,672.26) R22.1@3985.47,660.5 ; v1@3974.7,677.7 cw(c3961.89,664.89) 3980,664.89 cw(c3998.11,664.89) v1@3985.3,677.7 ; v1@3974.83,677.57 cw(c3970.08,672.58) 3976.73,670.8 cw(c3983.38,669.02) v1@3981.76,675.71 ; v1@3978.24,675.71 cw(c3976.62,669.02) 3983.27,670.8 cw(c3989.92,672.58) v1@3985.17,677.57 ; R22.1@3980,654 v1(3980,683) ; R22.1@3988.69,664.33 cw(c4004.39,683) v1(3980,683)
FPGA_TCK: R28.2 U6.C14 | length 1831.3
  Top Layer w5: v1@2321.04,1902.56 cw(c2318.54,1883.14) U6.C14@2335.49,1892.93 ; v1@2321.68,1907.52 cw(c2320.16,1895.75) 2330.44,1901.68 ; v1@2322,1902.5 cw(c2322,1884.39) 2334.8,1897.2 cw(c2347.61,1910) v1@2329.5,1910 ; v1(2322,1910) U6.C14@2341.46,1890.54 ; v1@2324.09,1902.8 cw(c2325.9,1896.57) 2331.52,1899.81 ; v1@2324.48,1910.32 ccw(c2336.25,1911.84) 2330.32,1901.56 ; v1@2329.2,1907.91 ccw(c2335.43,1906.1) 2332.19,1900.48 ; v1@2329.44,1910.96 ccw(c2348.86,1913.46) U6.C14@2339.07,1896.51 ; U6.C14@2335.11,1890.54 ccw(c2319.76,1890.54) 2330.61,1901.39 ccw(c2341.46,1912.24) U6.C14@2341.46,1896.89 ; v1@2323.94,1902.76 cw(c2325.84,1895.66) 2329.52,1902.02 ccw(c2325.84,1895.66) v1@2323.94,1902.76 ; v1@2329.24,1908.06 ccw(c2336.34,1906.16) 2329.98,1902.48 cw(c2336.34,1906.16) v1@2329.24,1908.06
  Mid-Layer 1 w5: v1@1946.5,3085 cw(c1928.39,3085) 1941.2,3072.2 cw(c1954,3059.39) v1@1954,3077.5 ; v1(1954,3085) 1841,2972 1841,2625 2178,2288 2178,2054 v1(2322,1910) ; v1@2314.5,1910 ccw(c2296.39,1910) 2309.2,1922.8 ccw(c2322,1935.61) v1@2322,1917.5
  Bottom Layer w5: R28.2@1934,3157 1954,3137 ; R28.2@1934.89,3148.55 cw(c1936.41,3134.22) 1946.59,3144.41 cw(c1956.78,3154.59) R28.2@1942.45,3156.11 ; R28.2@1935.42,3143.57 cw(c1937.82,3120.82) 1954,3137 ; R28.2@1947.43,3155.58 ccw(c1970.18,3153.18) 1954,3137 ; v1@1948.7,3090.3 ccw(c1935.89,3103.11) 1954,3103.11 ccw(c1972.11,3103.11) v1@1959.3,3090.3 ; v1(1954,3085) 1954,3137
FPGA_TDI: R48.2 U6.C12 | length 2063.3
  Top Layer w5: v1@2320.77,1824.05 cw(c2318.06,1804.07) U6.C12@2335.52,1814.15 ; v1@2321.44,1829 cw(c2319.79,1816.84) 2330.42,1822.98 ; v1@2321.78,1823.98 cw(c2321.78,1805.87) 2334.58,1818.68 cw(c2347.39,1831.48) v1@2329.28,1831.48 ; v1(2321.78,1831.48) U6.C12@2341.46,1811.8 ; v1@2323.75,1824.24 cw(c2325.56,1817.58) 2331.54,1821.03 ; v1@2324.26,1831.82 ccw(c2336.42,1833.47) 2330.28,1822.84 ; v1@2329.02,1829.51 ccw(c2335.68,1827.7) 2332.23,1821.72 ; v1@2329.21,1832.49 ccw(c2349.19,1835.2) U6.C12@2339.11,1817.74 ; U6.C12@2335.11,1811.8 ccw(c2319.76,1811.8) 2330.61,1822.65 ccw(c2341.46,1833.5) U6.C12@2341.46,1818.15 ; v1@2323.72,1824.24 cw(c2325.55,1817.41) 2329.08,1823.53 ccw(c2325.55,1817.41) v1@2323.72,1824.24 ; v1@2329.02,1829.54 ccw(c2335.85,1827.71) 2329.73,1824.18 cw(c2335.85,1827.71) v1@2329.02,1829.54
  Mid-Layer 1 w5: v1@2013.5,3083 cw(c1995.39,3083) 2008.2,3070.2 cw(c2021,3057.39) v1@2021,3075.5 ; v1(2021,3083) 1866,2928 1866,2643 2421,2088 2421,1862 2410,1851 2341.3,1851 v1(2321.78,1831.48) ; v1@2321.78,1838.98 ccw(c2321.78,1857.09) 2334.58,1844.28 ccw(c2347.39,1831.48) v1@2329.28,1831.48
  Bottom Layer w5: v1@2015.7,3088.3 ccw(c2002.89,3101.11) 2021,3101.11 ccw(c2039.11,3101.11) v1@2026.3,3088.3 ; v1(2021,3083) 2021,3124 R48.2@2054,3157 ; R48.2@2040.5,3157 cw(c2007.91,3157) 2030.95,3133.95 cw(c2054,3110.91) R48.2@2054,3143.5 ; R48.2@2045.5,3157 cw(c2024.98,3157) 2039.49,3142.49 cw(c2054,3127.98) R48.2@2054,3148.5
FPGA_TDO: R29.2 U6.E14 | length 1898.8
  Top Layer w5: v1@2399.51,1902.79 cw(c2396.8,1882.81) U6.E14@2414.26,1892.89 ; v1@2400.18,1907.74 cw(c2398.53,1895.58) 2409.16,1901.72 ; v1@2400.52,1902.72 cw(c2400.52,1884.61) 2413.32,1897.42 cw(c2426.13,1910.22) v1@2408.02,1910.22 ; v1(2400.52,1910.22) U6.E14@2420.2,1890.54 ; v1@2402.49,1902.98 cw(c2404.3,1896.32) 2410.28,1899.77 ; v1@2403,1910.56 ccw(c2415.16,1912.21) 2409.02,1901.58 ; v1@2407.76,1908.25 ccw(c2414.42,1906.44) 2410.97,1900.46 ; v1@2407.95,1911.23 ccw(c2427.93,1913.94) U6.E14@2417.85,1896.48 ; U6.E14@2413.85,1890.54 ccw(c2398.5,1890.54) 2409.35,1901.39 ccw(c2420.2,1912.24) U6.E14@2420.2,1896.89 ; v1@2402.46,1902.98 cw(c2404.29,1896.15) 2407.82,1902.27 ccw(c2404.29,1896.15) v1@2402.46,1902.98 ; v1@2407.76,1908.28 ccw(c2414.59,1906.45) 2408.47,1902.92 cw(c2414.59,1906.45) v1@2407.76,1908.28
  Mid-Layer 1 w5: v1@1979.5,3085 cw(c1961.39,3085) 1974.2,3072.2 cw(c1987,3059.39) v1@1987,3077.5 ; v1(1987,3085) 1853,2951 1853,2633 2400.52,2085.48 v1(2400.52,1910.22) ; v1@2395.22,1915.52 ccw(c2382.41,1928.33) 2400.52,1928.33 ccw(c2418.63,1928.33) v1@2405.82,1915.52
  Bottom Layer w5: v1@1981.7,3090.3 ccw(c1968.89,3103.11) 1987,3103.11 ccw(c2005.11,3103.11) v1@1992.3,3090.3 ; R29.2@1984.45,3147.45 cw(c1978.31,3141.31) R29.2@1987,3141.31 ; v1(1987,3085) R29.2@1987,3150 ; 1987,3107.51 cw(c2043.49,3107.51) R29.2@2003.55,3147.45 ; 1987,3119.58 cw(c2031.42,3119.58) R29.2@2000.01,3150.99 ; 1987,3131.65 cw(c2019.35,3131.65) R29.2@1996.47,3154.53
FPGA_TMS: R8.2 U6.A15 | length 1710.5
  Top Layer w5: v1(2223.09,1929.91) U6.A15@2262.72,1929.91 ; v1@2228.4,1924.6 cw(c2241.2,1911.8) 2241.2,1929.91 cw(c2241.2,1948.01) v1@2228.4,1935.21 ; U6.A15@2258.23,1925.41 ccw(c2247.37,1914.56) 2247.37,1929.91 ccw(c2247.37,1945.26) U6.A15@2258.23,1934.4
  Mid-Layer 1 w5: v1@1916.5,3085 cw(c1898.39,3085) 1911.2,3072.2 cw(c1924,3059.39) v1@1924,3077.5 ; v1(1924,3085) 1830,2991 1830,2608 2160,2278 2160,1993 v1(2223.09,1929.91) ; v1@2215.59,1929.91 ccw(c2197.49,1929.91) 2210.29,1942.71 ccw(c2223.09,1955.51) v1@2223.09,1937.41
  Bottom Layer w5: R8.2@1874,3143.5 cw(c1874,3110.91) 1897.05,3133.95 cw(c1920.09,3157) R8.2@1887.5,3157 ; R8.2@1874,3148.5 cw(c1874,3127.98) 1888.51,3142.49 cw(c1903.02,3157) R8.2@1882.5,3157 ; R8.2@1874,3157 1924,3107 v1(1924,3085) ; v1@1918.7,3090.3 ccw(c1905.89,3103.11) 1924,3103.11 ccw(c1942.11,3103.11) v1@1929.3,3090.3
G11: J5.9 U6.G11 | length 1966.7
  Top Layer w5: v1@2478.25,1784.68 cw(c2475.54,1764.7) U6.G11@2493,1774.78 ; v1@2478.92,1789.63 cw(c2477.27,1777.47) 2487.9,1783.61 ; v1@2479.26,1784.61 cw(c2479.26,1766.5) 2492.06,1779.31 cw(c2504.87,1792.11) v1@2486.76,1792.11 ; v1(2479.26,1792.11) U6.G11@2498.94,1772.43 ; v1@2481.23,1784.87 cw(c2483.04,1778.21) 2489.02,1781.66 ; v1@2481.74,1792.45 ccw(c2493.9,1794.1) 2487.76,1783.47 ; v1@2486.69,1793.12 ccw(c2506.67,1795.83) U6.G11@2496.59,1778.37 ; 2489.71,1782.35 cw(c2493.16,1788.33) v1@2486.5,1790.14 ; U6.G11@2492.59,1772.43 ccw(c2477.24,1772.43) 2488.09,1783.28 ccw(c2498.94,1794.13) U6.G11@2498.94,1778.78 ; v1@2486.5,1790.17 ccw(c2493.33,1788.34) 2487.21,1784.81 cw(c2493.33,1788.34) v1@2486.5,1790.17 ; v1@2481.2,1784.87 cw(c2483.03,1778.04) 2486.56,1784.16 ccw(c2483.03,1778.04) v1@2481.2,1784.87
  Bottom Layer w5: v1(2479.26,1792.11) 2500.15,1813 2526,1813 2557,1844 2557,2330 2855,2628 2855,3061.17 J5.9@2903,3109.17 ; v1@2479.26,1799.61 ccw(c2479.26,1817.72) 2492.06,1804.91 ccw(c2504.87,1792.11) v1@2486.76,1792.11 ; J5.9@2875.97,3109.17 cw(c2810.72,3109.17) 2856.86,3063.03 cw(c2903,3016.9) J5.9@2903,3082.15 ; J5.9@2880.97,3109.17 cw(c2827.79,3109.17) 2865.4,3071.57 cw(c2903,3033.97) J5.9@2903,3087.15 ; J5.9@2885.97,3109.17 cw(c2844.86,3109.17) 2873.93,3080.11 cw(c2903,3051.04) J5.9@2903,3092.15
G12: J5.12 U6.G12 | length 1786.1
  Top Layer w5: v1@2478.25,1824.05 cw(c2475.54,1804.07) U6.G12@2493,1814.15 ; v1@2478.92,1829 cw(c2477.27,1816.84) 2487.9,1822.98 ; v1@2479.26,1823.98 cw(c2479.26,1805.87) 2492.06,1818.68 cw(c2504.87,1831.48) v1@2486.76,1831.48 ; v1(2479.26,1831.48) U6.G12@2498.94,1811.8 ; v1@2481.23,1824.24 cw(c2483.04,1817.58) 2489.02,1821.03 ; v1@2481.74,1831.82 ccw(c2493.9,1833.47) 2487.76,1822.84 ; v1@2486.5,1829.51 ccw(c2493.16,1827.7) 2489.71,1821.72 ; v1@2486.69,1832.49 ccw(c2506.67,1835.2) U6.G12@2496.59,1817.74 ; U6.G12@2492.59,1811.8 ccw(c2477.24,1811.8) 2488.09,1822.65 ccw(c2498.94,1833.5) U6.G12@2498.94,1818.15 ; v1@2481.2,1824.24 cw(c2483.03,1817.41) 2486.56,1823.53 ccw(c2483.03,1817.41) v1@2481.2,1824.24 ; v1@2486.5,1829.54 ccw(c2493.33,1827.71) 2487.21,1824.18 cw(c2493.33,1827.71) v1@2486.5,1829.54
  Bottom Layer w5: v1(2479.26,1831.48) 2497.78,1850 2524,1850 2547,1873 2547,2346 2803,2602 J5.12@2803,3009.17 ; v1@2479.26,1838.98 ccw(c2479.26,1857.09) 2492.06,1844.28 ccw(c2504.87,1831.48) v1@2486.76,1831.48 ; J5.12@2783.89,2990.06 cw(c2737.75,2943.92) 2803,2943.92 cw(c2868.25,2943.92) J5.12@2822.11,2990.06 ; J5.12@2787.42,2993.6 cw(c2749.82,2955.99) 2803,2955.99 cw(c2856.18,2955.99) J5.12@2818.58,2993.6 ; J5.12@2790.96,2997.13 cw(c2761.89,2968.07) 2803,2968.07 cw(c2844.11,2968.07) J5.12@2815.04,2997.13
G14: J5.16 U6.G14 | length 1580.7
  Top Layer w5: v1@2478.25,1902.79 cw(c2475.54,1882.81) U6.G14@2493,1892.89 ; v1@2478.92,1907.74 cw(c2477.27,1895.58) 2487.9,1901.72 ; v1@2479.26,1902.72 cw(c2479.26,1884.61) 2492.06,1897.42 cw(c2504.87,1910.22) v1@2486.76,1910.22 ; v1(2479.26,1910.22) U6.G14@2498.94,1890.54 ; v1@2481.23,1902.98 cw(c2483.04,1896.32) 2489.02,1899.77 ; v1@2481.74,1910.56 ccw(c2493.9,1912.21) 2487.76,1901.58 ; v1@2486.5,1908.25 ccw(c2493.16,1906.44) 2489.71,1900.46 ; v1@2486.69,1911.23 ccw(c2506.67,1913.94) U6.G14@2496.59,1896.48 ; U6.G14@2492.59,1890.54 ccw(c2477.24,1890.54) 2488.09,1901.39 ccw(c2498.94,1912.24) U6.G14@2498.94,1896.89 ; v1@2481.2,1902.98 cw(c2483.03,1896.15) 2486.56,1902.27 ccw(c2483.03,1896.15) v1@2481.2,1902.98 ; v1@2486.5,1908.28 ccw(c2493.33,1906.45) 2487.21,1902.92 cw(c2493.33,1906.45) v1@2486.5,1908.28
  Bottom Layer w5: v1(2479.26,1910.22) 2479.26,1919.26 2499,1939 2499,2553 2603,2657 J5.16@2603,3009.17 ; J5.16@2583.89,2990.06 cw(c2537.75,2943.92) 2603,2943.92 cw(c2668.25,2943.92) J5.16@2622.11,2990.06 ; J5.16@2587.42,2993.6 cw(c2549.82,2955.99) 2603,2955.99 cw(c2656.18,2955.99) J5.16@2618.58,2993.6 ; J5.16@2590.96,2997.13 cw(c2561.89,2968.07) 2603,2968.07 cw(c2644.11,2968.07) J5.16@2615.04,2997.13
G16: RN12.8 U6.G16 | length 2293.3
  Top Layer w5: RN12.8@541.15,2316.62 568.84,2316.62 629.21,2377 2257,2377 2498.94,2135.06 U6.G16@2498.94,1969.28 ; RN12.8@556.76,2312.83 cw(c565.93,2303.65) 565.93,2316.62 cw(c565.93,2329.6) RN12.8@556.76,2320.42 ; U6.G16@2494.45,1973.77 ccw(c2483.59,1984.63) 2498.94,1984.63 ccw(c2514.3,1984.63) U6.G16@2503.44,1973.77
GND: C1.2 C2.2 C3.2 C4.1 C5.2 C6.2 C7.2 C8.2 C9.2 C10.2 C11.2 C12.2 C13.2 C14.2 C15.2 C16.2 C17.2 C18.2 C19.2 C20.2 C25.2 C27.2 C29.2 C30.2 C31.2 C32.2 C33.2 C34.2 C35.2 C36.2 C37.2 C38.2 C39.2 C40.2 C41.2 C42.2 C43.2 C44.2 C45.2 C46.2 C48.2 C49.2 D1.1 EC2.2 EC4.2 EC5.2 EC6.2 J1.5 J2.1 J2.37 J2.38 J3.1 J3.37 J3.38 J4.5 J4.6 J4.7 J4.8 J4.10 J5.2 K1.2 K2.2 K3.1 K4.2 K5.2 K6.1 LED0.2 LED1.2 LED2.2 LED3.2 LED6.2 LS1.2 P1.1 P2.1 P4.1 P5.1 P5.3 P5.5 P5.7 P5.9 P5.11 P5.13 R10.1 R20.1 R49.2 R51.2 U1.1 U2.2 U4.3 U5.1 U6.A1 U6.A16 U6.B7 U6.B11 U6.D4 U6.D13 U6.E9 U6.G2 U6.G8 U6.G15 U6.H7 U6.H9 U6.H12 U6.J5 U6.J8 U6.K7 U6.K9 U6.L2 U6.L15 U6.M8 U6.N13 U6.P3 U6.R6 U6.R10 U6.T1 U6.T16 U8.4 U9.6 U9.12 U9.28 U9.41 U9.46 U9.52 U9.54 U10.2 U11.4 U12.1 U12.2 U12.3 U12.4 U12.7 U14.6 U14.11 U14.12 U14.13 X1.2 Y1.0 | length 8366.7
  Top Layer w10: v1@697.09,2854.09 cw(c688.56,2845.56) 700.63,2845.56 cw(c712.7,2845.56) v1@704.17,2854.09 ; U4.3@700.63,2814 v1(700.63,2857.63) ; LED1.2@3878.33,897 v2@3933,897 ; LED1.2@3892.48,882.86 cw(c3926.62,848.72) 3926.62,897 cw(c3926.62,945.28) LED1.2@3892.48,911.14 ; 3907.29,891.82 cw(c3913.63,868.16) v2@3928.1,887.93 ; 3907.44,897 cw(c3907.44,869.44) v2@3926.93,888.93 ; 3908.23,901.93 ccw(c3915.32,928.36) v2@3929,904.66 ; 3912.27,897 ccw(c3912.27,917.73) v2@3926.93,903.07 ; 3912.64,900.75 cw(c3907.23,880.54) v2@3925.34,891 ; 3916.64,894.33 ccw(c3912.94,908.16) v2@3925.34,901 ; LED2.2@4116.67,897 v2(4173,897) ; LED2.2@4130.81,882.86 cw(c4164.95,848.72) 4164.95,897 cw(c4164.95,945.28) LED2.2@4130.81,911.14 ; 4144.3,891.47 cw(c4152.38,861.31) v2@4168,888.34 ; 4144.3,902.53 ccw(c4152.38,932.69) v2@4168,905.66 ; 4154,894.07 ccw(c4149.59,910.51) v2@4164.34,902 ; 4154,899.93 cw(c4149.59,883.49) v2@4164.34,892 ; v2@4165.93,889.93 ccw(c4148.86,872.86) 4148.86,897 ccw(c4148.86,921.14) v2@4165.93,904.07 ; LED3.2@4355,897 v2@4411,897 ; LED3.2@4369.14,882.86 cw(c4403.28,848.72) 4403.28,897 cw(c4403.28,945.28) LED3.2@4369.14,911.14 ; 4384.53,902.02 ccw(c4391.1,926.52) v2@4406.09,906.07 ; 4385.34,892.19 cw(c4392.73,864.62) v2@4407,889.34 ; 4385.44,897 ccw(c4385.44,924.56) v2@4404.93,905.07 ; 4390.27,897 cw(c4390.27,876.27) v2@4404.93,890.93 ; 4391.35,893.8 ccw(c4386.25,912.87) v2@4403.34,903 ; 4395.36,899.12 cw(c4391.96,886.43) v2@4403.34,893
  Top Layer w15: P2.1@1776.42,3066.42 cw(c1738.82,3028.82) 1792,3028.82 cw(c1845.18,3028.82) P2.1@1807.58,3066.42 ; C45.2@1781.46,3004.78 ccw(c1756.03,3030.21) 1792,3030.21 ; C45.2@1785,3001.24 1792,3008.24 P2.1@1792,3082 ; v2(1973,2095) 1976,2092 U11.4@2034,2092 ; v2@1978.3,2100.3 ccw(c1998.35,2120.35) 1998.35,2092 ; v1@2223.63,1969.28 U6.A16@2262.72,1969.28 ; v1(2262.72,1339.35) U6.A1@2262.72,1378.72 ; P4.1@2283.42,3063.42 cw(c2245.82,3025.82) 2299,3025.82 cw(c2352.18,3025.82) P4.1@2314.58,3063.42 ; C49.2@2294.46,2995.78 ccw(c2283.51,3006.73) 2299,3006.73 ; C49.2@2298,2992.24 2299,2993.24 P4.1@2299,3079 ; v2(2395,2413) D1.1@2452,2413 ; v2@2398.75,2406.5 cw(c2408.99,2388.77) 2414.29,2408.55 ; v2@2398.75,2419.5 ccw(c2408.99,2437.23) 2414.29,2417.45 ; v2@2400.3,2407.7 cw(c2413.11,2394.89) 2413.11,2413 cw(c2413.11,2431.11) v2@2400.3,2418.3 ; v2@2401.5,2409.25 cw(c2415.12,2401.38) 2411.05,2416.58 ; v2@2401.5,2416.75 ccw(c2415.12,2424.62) 2411.05,2409.42 ; D1.1@2436.09,2397.09 ccw(c2397.68,2358.68) 2397.68,2413 ccw(c2397.68,2467.32) D1.1@2436.09,2428.91 ; U9.54@2545,897 2545,860 2572,833 v2(2608,833) U9.52@2607.99,897 ; U9.54@2546,868 ccw(c2567.73,868) 2552.36,852.64 ; v2@2602.7,827.7 ccw(c2589.89,814.89) 2589.89,833 ccw(c2589.89,851.11) 2602.7,838.3 ccw(c2589.91,851.09) 2607.99,851.09 ; 2607.99,851.13 ccw(c2626.13,851.13) v2@2613.3,838.3 ; v2@2697.18,381.82 ccw(c2684.37,394.63) 2702.48,394.63 ccw(c2720.59,394.63) v2@2707.78,381.82 ; v2(2702.48,376.52) U9.6@2702.48,437 ; v2@2791.67,955.7 cw(c2778.86,942.89) 2796.97,942.89 cw(c2815.08,942.89) v2@2802.27,955.7 ; v2@2795.37,968.33 ccw(c2789.11,997.13) C35.2@2813.9,981.19 ; U9.46@2796.97,897 2796.97,973.21 C35.2@2813.76,990 ccw(c2837.12,966.63) v2@2804.4,962.04 ; 2796.97,937.4 cw(c2866.36,937.4) C35.2@2817.29,986.46 ; v2@2796.97,966.26 cw(c2815.8,966.26) C35.2@2814.18,985.02 ; v2@2796.97,973.61 cw(c2830.14,973.61) C35.2@2806.68,997.07 ; 2799.95,984.74 ccw(c2823.1,978.53) v2@2803.2,965.18 ; U6.T1@2853.28,1378.72 v1@2890.72,1378.72 ; U6.T16@2853.28,1969.28 v1(2876,1992) ; v2@2886.15,380.85 ccw(c2873.35,393.65) 2891.46,393.65 ccw(c2909.56,393.65) v2@2896.76,380.85 ; v2(2891.46,375.54) U9.12@2891.46,437 ; v2@2949.15,843.3 ccw(c2936.34,856.11) 2954.45,856.11 ccw(c2972.56,856.11) v2@2959.75,843.3 ; v2(2954.45,838) U9.41@2954.45,907.55 ; v2(3334,826) 3363.9,855.9 U9.28@3363.9,897 ; v2@3334,833.5 ccw(c3334,851.61) 3346.8,838.8 ccw(c3359.61,826) v2@3341.5,826 ; X1.2@3334,1633 X1.2@3345,1622 ; 3353.63,845.63 ccw(c3331.27,868) U9.28@3362.9,868 ; R20.1@3445,1897 v1(3484,1897) ; R20.1@3451.01,1890.99 cw(c3465.52,1876.48) 3465.52,1897 cw(c3465.52,1917.52) R20.1@3451.01,1903.01 ; C37.2@3580,2608.24 v1(3580,2631) ; LED0.2@3640,897 v2@3690,897 ; LED0.2@3652.37,884.63 cw(c3682.25,854.75) 3682.25,897 cw(c3682.25,939.25) LED0.2@3652.37,909.37 ; 3666.53,901.21 ccw(c3673.2,926.09) v2@3686.99,904.34 ; 3670.14,893.76 cw(c3675.98,871.98) v2@3687.25,891.5 ; 3670.48,897 ccw(c3670.48,918.52) v2@3685.7,903.3 ; 3675.31,897 cw(c3675.31,882.31) v2@3685.7,892.7 ; 3676.2,895.38 ccw(c3672.67,908.59) v2@3684.5,901.75 ; C3.2@3724.24,1551 v2@3805,1551 ; C46.2@3747.99,1501.01 ccw(c3733.48,1515.52) 3754,1515.52 ccw(c3774.52,1515.52) C46.2@3760.01,1501.01 ; C46.2@3754,1495 3754,1549 ; 3784.48,1551 cw(c3784.48,1529.48) v2@3799.7,1544.7 ; 3789.31,1551 ccw(c3789.31,1565.69) v2@3799.7,1555.3 ; U8.4@4140,1455 v1(4185,1455) ; v2@4325.74,517.35 ccw(c4312.94,530.15) 4331.05,530.15 ccw(c4349.15,530.15) v2@4336.35,517.35 ; v2(4331.05,512.05) U14.6@4331.05,568.82 ; v2@4411.7,728.7 cw(c4398.89,715.89) 4417,715.89 cw(c4435.11,715.89) v2@4422.3,728.7 ; C43.2@4417,697.24 v2(4417,734) ; v2@4436.7,1531.3 ccw(c4423.89,1544.11) 4442,1544.11 ccw(c4460.11,1544.11) v2@4447.3,1531.3 ; v2(4442,1526) C4.1@4442,1559
  Top Layer w17.72: v1(2284,1596.85) U6.B7@2302.09,1614.94 ; v1(2284,1790.52) U6.B11@2302.09,1772.43 ; v1(2361.15,1477.15) U6.D4@2380.83,1496.83 ; v1(2361.15,1870.85) U6.D13@2380.83,1851.17 ; v1(2400.52,1713.37) U6.E9@2420.2,1693.68 ; v1(2479.26,1634.63) U6.G8@2498.94,1654.32 ; v1(2479.85,1399) U6.G2@2498.94,1418.09 ; v1(2481,1947.85) U6.G15@2498.94,1929.91 ; v1(2518.63,1595.26) U6.H7@2538.32,1614.94 ; v1(2518.63,1713.37) U6.H9@2538.32,1693.68 ; v1(2518.63,1831.48) U6.H12@2538.32,1811.8 ; U6.J5@2577.68,1536.2 v1(2597.37,1516.52) ; U6.J8@2577.68,1654.32 v1(2597.37,1634.63) ; U9.52@2607.99,897 2607.99,980.24 C34.2@2619.76,992 ; 2607.99,954.81 cw(c2656.95,954.81) C34.2@2622.33,989.42 ; U6.K7@2617.06,1614.94 v1(2636.74,1595.26) ; U6.K9@2617.06,1693.68 v1(2636.74,1713.37) ; U6.L2@2656.43,1418.09 v1@2673.52,1401 ; U6.L15@2656.43,1929.91 v1(2674.52,1948) ; U6.M8@2695.8,1654.32 v1(2715.48,1634.63) ; U6.N13@2735.17,1851.17 v1(2754.85,1870.85) ; U6.P3@2774.54,1457.46 v1(2794.22,1437.78) ; U6.R6@2813.91,1575.57 v1(2831.48,1558) ; U6.R10@2813.91,1733.06 v1(2832,1751.15)
  Top Layer w19.68: v3(453,2883) C1.2@499,2883 501.94,2883 C2.2@501.94,2949 ; v3@460.18,2875.82 cw(c477.52,2858.48) 477.52,2883 cw(c477.52,2907.52) v3@460.18,2890.18 ; C2.2@493.59,2935.53 cw(c473.43,2915.37) 501.94,2915.37 cw(c530.46,2915.37) C2.2@510.3,2935.53 ; C1.2@494.65,2887.35 ccw(c477.02,2904.98) 501.94,2904.98 ; LED6.2@1295,3090 1329,3056 ; LED6.2@1295.14,3069.84 cw(c1295.58,3022.58) 1329,3056 ; LED6.2@1310.16,3085 ccw(c1334.68,3085) LED6.2@1317.34,3067.66 ; v2(1390,3056) 1329,3056
  Top Layer w20: K1.2@1454.58,89.58 cw(c1424.61,59.61) 1467,59.61 cw(c1509.39,59.61) K1.2@1479.42,89.58 ; v2@1462.67,53.09 ccw(c1445.31,63.11) 1464.67,68.3 ; v2(1467,50.59) K1.2@1467,102 ; 1469.33,68.3 ccw(c1488.69,63.11) v2@1471.33,53.09 ; K2.2@2022.25,89.58 cw(c1992.28,59.61) 2034.67,59.61 cw(c2077.06,59.61) K2.2@2047.08,89.58 ; v2@2030.34,53.09 ccw(c2012.98,63.11) 2032.34,68.3 ; v2(2034.67,50.59) K2.2@2034.67,102 ; 2036.99,68.3 ccw(c2056.35,63.11) v2@2039,53.09 ; v2@2512,298.76 C30.2@2545,298.76 ; K3.1@2589.92,86.79 cw(c2559.94,56.81) 2602.33,56.81 cw(c2644.72,56.81) K3.1@2614.75,86.79 ; v2@2598,47.7 ccw(c2578.67,58.87) 2600.23,64.65 ; v2(2602.33,45.2) K3.1@2602.33,99.2 ; 2604.43,64.65 ccw(c2626,58.87) v2@2606.66,47.7 ; C29.2@2607.99,297.76 2607.99,298 v2(2645,298) ; C31.2@2797,297.76 v2(2824.24,297.76) ; C32.2@2955,300.76 v2(2990.76,300.76) ; K4.2@3157.58,89.58 cw(c3127.61,59.61) 3170,59.61 cw(c3212.39,59.61) K4.2@3182.42,89.58 ; v2@3165.67,53.09 ccw(c3148.31,63.11) 3167.67,68.3 ; v2(3170,50.59) K4.2@3170,102 ; 3172.33,68.3 ccw(c3191.69,63.11) v2@3174.33,53.09 ; U12.4@3277,2412 U12.3@3277,2462 U12.2@3277,2512 U12.1@3277,2562 v2(3277,2606) ; C33.2@3364,300.76 v2(3392.76,300.76) ; U12.7@3497,2512 v1(3546,2512) ; K6.1@3690.58,453.58 cw(c3660.61,423.61) 3703,423.61 cw(c3745.39,423.61) K6.1@3715.42,453.58 ; K5.2@3693.58,93.58 cw(c3663.61,63.61) 3706,63.61 cw(c3748.39,63.61) K5.2@3718.42,93.58 ; v2@3698.67,414.5 ccw(c3679.33,425.66) 3700.9,431.44 ; v2@3701.67,57.09 ccw(c3684.31,67.11) 3703.67,72.3 ; v2(3703,412) K6.1@3703,466 ; 3705.1,431.44 ccw(c3726.67,425.66) v2@3707.33,414.5 ; v2(3706,54.59) K5.2@3706,106 ; 3708.33,72.3 ccw(c3727.69,67.11) v2@3710.33,57.09
  Bottom Layer w10: v1(2183,1872) C13.2@2210.76,1872 ; v1@2186.22,1868.18 cw(c2194.28,1858.61) 2197.52,1870.69 ; v1@2186.22,1875.82 ccw(c2194.28,1885.39) 2197.52,1873.31 ; v1@2186.54,1868.46 cw(c2195.07,1859.93) 2195.07,1872 cw(c2195.07,1884.07) v1@2186.54,1875.54 ; C14.2@2203.45,1718.3 ccw(c2190.65,1731.11) 2208.76,1731.11 ccw(c2226.86,1731.11) C14.2@2214.06,1718.3 ; v1@2205.22,1787.22 cw(c2196.68,1778.68) 2208.76,1778.68 cw(c2220.83,1778.68) v1@2212.29,1787.22 ; C13.2@2205.45,1866.7 ccw(c2192.65,1853.89) 2192.65,1872 ccw(c2192.65,1890.11) C13.2@2205.45,1877.3 ; C14.2@2208.76,1713 v1(2208.76,1790.76) ; C12.2@2355.7,2031.55 ccw(c2342.89,2044.35) 2361,2044.35 ccw(c2379.11,2044.35) C12.2@2366.3,2031.55 ; v1@2357.46,2058.46 cw(c2348.93,2049.93) 2361,2049.93 cw(c2373.07,2049.93) v1@2364.54,2058.46 ; C12.2@2361,2026.24 v1(2361,2062) ; C11.2@2634.33,1987.77 cw(c2632.73,1969.74) 2646.62,1981.36 cw(c2660.51,1992.97) C11.2@2642.47,1994.58 ; C11.2@2635,1995.24 v1(2674.52,1948) ; v1@2669.54,1948.44 ccw(c2657.52,1949.51) 2666.77,1957.26 ccw(c2676.03,1965) v1@2674.96,1952.98 ; v1@2832,1746.15 cw(c2832,1734.08) 2840.54,1742.61 cw(c2849.07,1751.15) v1@2837,1751.15 ; v1(2832,1751.15) 2857.15,1726 2930,1726 R51.2@2956,1752 ; R51.2@2945,1752 cw(c2918.44,1752) 2937.22,1733.22 cw(c2956,1714.44) R51.2@2956,1741 ; v2@3992.93,2902.93 cw(c3975.86,2885.86) 4000,2885.86 cw(c4024.14,2885.86) v2@4007.07,2902.93 ; 4000,2875 v2(4000,2910)
  Bottom Layer w15: v2@2117.45,2269.45 cw(c2104.65,2256.65) 2122.76,2256.65 cw(c2140.86,2256.65) v2@2128.06,2269.45 ; C36.2@2122.76,2242 v2(2122.76,2274.76) ; R49.2@2205,1428 2236.76,1459.76 C16.2@2236.76,1507 ; R49.2@2205,1436.5 ccw(c2205,1457.02) 2219.51,1442.51 ccw(c2234.02,1428) R49.2@2213.5,1428 ; C17.2@2598,1321.76 C18.2@2754,1321.76 ; C5.2@2603.99,2112.06 ccw(c2579.83,2136.22) 2614,2136.22 ccw(c2648.17,2136.22) C5.2@2624.01,2112.06 ; C5.2@2614,2102.06 v1(2614,2159) ; 2677,1323.76 v1(2677,1353) ; C38.2@3956,2875 4000,2875 4090,2875 ; C38.2@3961.01,2869.99 cw(c3973.11,2857.89) 3973.11,2875 ; C38.2@3961.01,2882.01 ccw(c3977.94,2898.93) 3977.94,2875 ; 4022.06,2875 ccw(c4022.06,2898.93) C39.2@4038.99,2882.01 ; 4026.89,2875 cw(c4026.89,2857.89) C39.2@4038.99,2869.99 ; C39.2@4051.01,2869.99 cw(c4063.11,2857.89) 4063.11,2875 ; C39.2@4051.01,2882.01 ccw(c4067.94,2898.93) 4067.94,2875 ; v2@4085.7,2907.7 cw(c4075.31,2897.31) 4090,2897.31 ; 4090,2892.48 cw(c4111.52,2892.48) v2@4096.3,2907.7 ; v2@4090,2912 4090,2875 ; C40.2@4128.99,2868.99 ccw(c4114.48,2854.48) 4114.48,2875 ccw(c4114.48,2895.52) C40.2@4128.99,2881.01 ; C41.2@4135,3404 4179.5,3404 ; C41.2@4141.01,3397.99 cw(c4155.52,3383.48) 4155.52,3404 cw(c4155.52,3424.52) C41.2@4141.01,3410.01 ; C40.2@4149,2875 C40.2@4135,2875 4090,2875 ; v2@4174.2,3385.8 ccw(c4161.39,3398.61) 4179.5,3398.61 ccw(c4197.61,3398.61) v2@4184.8,3385.8 ; v2(4179.5,3380.5) 4179.5,3404 ; 4202.06,3404 ccw(c4202.06,3427.93) C42.2@4218.99,3411.01 ; 4206.89,3404 cw(c4206.89,3386.89) C42.2@4218.99,3398.99 ; C42.2@4224,3404 4179.5,3404
  Bottom Layer w17.72: C19.2@2171,1582.94 2184.91,1596.85 v1(2212.15,1596.85) ; C19.2@2188.36,1579.22 cw(c2212.15,1571.99) v1(2212.15,1596.85) ; C16.2@2236.76,1507 2236.76,1593.61 ; v1(2284,1596.85) v1(2212.15,1596.85) ; v1(2361.15,1287.15) C15.2@2361.15,1321.76
  Bottom Layer w19.68: U2.2@697,3082.4 726.6,3082.4 749,3060 v3(749,2997) ; U2.2@712.16,3082.4 cw(c712.16,3047.54) 736.81,3072.19 ; v3@741.82,3004.18 ccw(c724.48,3021.52) 749,3021.52 ccw(c773.52,3021.52) v3@756.18,3004.18 ; C6.2@2519.24,1677 2519.24,1712.76 C8.2@2556,1712.76 ; C7.2@2558,1638.24 2593.76,1638.24 2596.76,1635.24 C9.2@2596.76,1677 ; C10.2@2755,2022.24 v1(2755,2047) ; R10.1@2874,1952 2874,1913.24 C20.2@2886.24,1901 ; C27.2@2913.24,1479 v1(2940,1479) ; C25.2@2914.24,1634 v1(2943,1634)
  Bottom Layer w20: R10.1@2869.76,1956.24 ccw(c2854.69,1971.31) 2876,1971.31 ; R10.1@2874,1952 2876,1954 v1(2876,1992)
  other v1: 4592,278 4458,283 4301,288 783,503 785,672 788,845 791,984 793.49,1358 715,1361 2892,1380 2676,1399 3398,1593 3398,1618 3398,1646 2223.35,1969 4237.71,2015 3166,2016 3240,2016 4070,2016 3098,2017 3862,2019 1932,2284.24 1680,2286 1796,2288 4118,2352 4272,2352 4419,2352 2791,2358 2905,2472 892,2479 1049,2479 754,2483 2136,2530 1603,2534
  other v2: 4764,241 4156,244 4763,287 4155,289 2512,298 4731,458 4730,501 3934,896 3691,898 4412,898 2796.97,961 3805,1550 1678,2165 679,2214 741,2214 679,2259 742,2259 1648,2497 2171,2497 1567,2498 2101,2498 2169,2568 2103,2570 1646,2572 1566,2574 1943,2888 1908,2912 4091,2913 1942,2938 1442,3055 1490,3055 501,3070 537,3071 501,3108 537,3109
